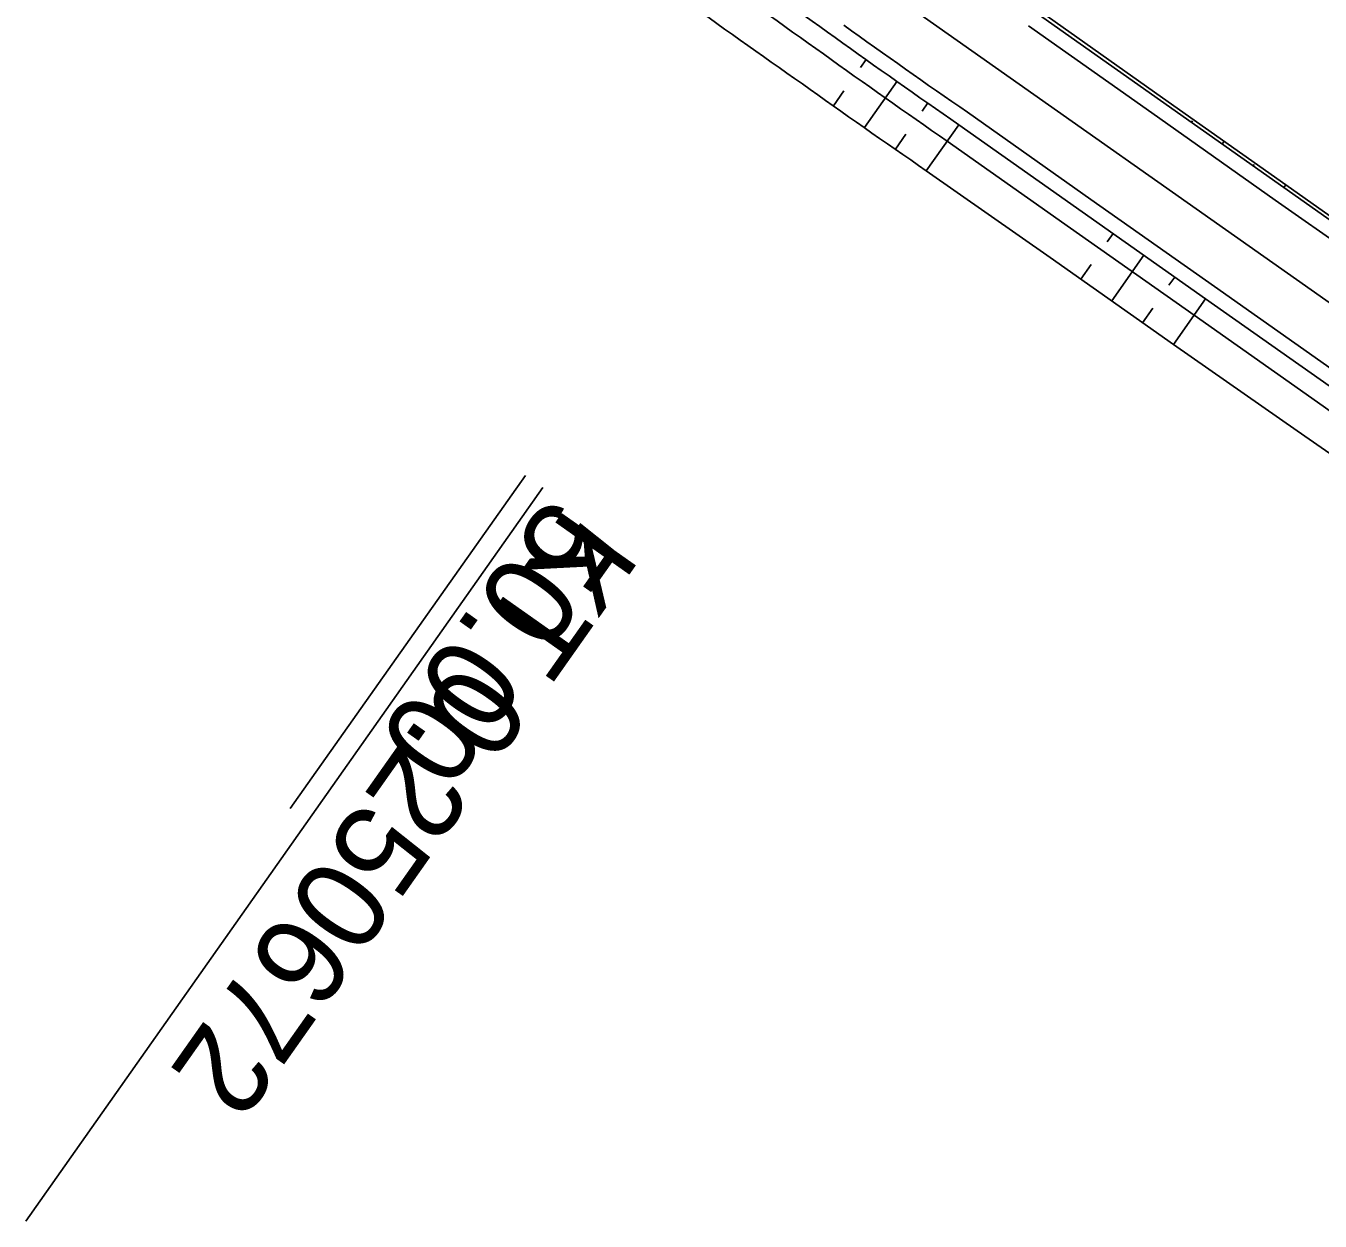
# Model space of a CAD drawing. Extents: x -481645 to -478728, y -1113199 to -1110710.
# Drawn here: x -480796.28 to -480753.43, y -1112781.89 to -1112742.33 of the extents above; entities that cross this region are included whole.
import ezdxf

# ---------------------------------------------------------------- set-up
doc = ezdxf.new("R2010")
doc.units = 0
for name, color, linetype in [('CP14_HATCH_SLOPE_R', 7, 'Continuous'), ('Vrstva 31', 7, 'Continuous'), ('Vrstva 32', 7, 'Continuous'), ('Vrstva 33', 7, 'Continuous'), ('Vrstva 34', 7, 'Continuous'), ('Vrstva 35', 7, 'Continuous'), ('Vrstva 36', 7, 'Continuous'), ('Vrstva 37', 7, 'Continuous'), ('Vrstva 39', 7, 'Continuous'), ('Vrstva 40', 7, 'Continuous')]:
    doc.layers.add(name, color=color, linetype=linetype)

msp = doc.modelspace()

# ---------------------------------------------------------------- linework, layer by layer
at = {"layer": 'CP14_HATCH_SLOPE_R'}
msp.add_line((-480767.637, -1112741.271), (-480724.708, -1112771.538), dxfattribs=at)
at = {"layer": 'Vrstva 31'}
for p, q in [((-480762.731, -1112741.823), (-480758.649, -1112744.712)), ((-480758.649, -1112744.712), (-480754.566, -1112747.598)), ((-480766.47, -1112747.127), (-480762.374, -1112749.995)), ((-480754.566, -1112747.598), (-480750.485, -1112750.486)), ((-480762.374, -1112749.995), (-480758.292, -1112752.882)), ((-480758.292, -1112752.882), (-480754.188, -1112755.739)), ((-480754.188, -1112755.739), (-480750.091, -1112758.604))]:
    msp.add_line(p, q, dxfattribs=at)
for centre, radius, start, end in [((-480480.966, -1112331.599), 504.14, 234.36572, 234.93868), ((-480624.003, -1112539.183), 252.066, 234.44634, 235.58416)]:
    msp.add_arc(centre, radius, start, end, dxfattribs=at)
at = {"layer": 'Vrstva 32'}
for p, q in [((-480765.78, -1112746.148), (-480761.694, -1112749.03)), ((-480761.694, -1112749.03), (-480757.607, -1112751.911)), ((-480757.607, -1112751.911), (-480753.521, -1112754.792)), ((-480753.521, -1112754.792), (-480749.434, -1112757.673))]:
    msp.add_line(p, q, dxfattribs=at)
for centre, radius, start, end in [((-480479.523, -1112332.626), 502.916, 234.16444, 234.7374), ((-480622.916, -1112539.216), 251.458, 234.23904, 235.37923)]:
    msp.add_arc(centre, radius, start, end, dxfattribs=at)
at = {"layer": 'Vrstva 33'}
for p, q in [((-480762.803, -1112741.926), (-480758.717, -1112744.807)), ((-480758.717, -1112744.807), (-480754.63, -1112747.688)), ((-480765.396, -1112745.604), (-480761.31, -1112748.485)), ((-480754.63, -1112747.688), (-480750.544, -1112750.569)), ((-480761.31, -1112748.485), (-480757.223, -1112751.366)), ((-480757.223, -1112751.366), (-480753.137, -1112754.247))]:
    msp.add_line(p, q, dxfattribs=at)
for centre, radius, start, end in [((-480479.523, -1112332.626), 502.25, 234.16444, 234.7374), ((-480622.724, -1112538.944), 251.125, 234.23839, 235.37989)]:
    msp.add_arc(centre, radius, start, end, dxfattribs=at)
at = {"layer": 'Vrstva 34'}
for p, q in [((-480763.091, -1112742.335), (-480759.005, -1112745.216)), ((-480765.108, -1112745.195), (-480761.021, -1112748.076)), ((-480759.005, -1112745.216), (-480754.918, -1112748.097)), ((-480761.021, -1112748.076), (-480756.935, -1112750.957)), ((-480754.918, -1112748.097), (-480750.832, -1112750.978)), ((-480756.935, -1112750.957), (-480752.849, -1112753.838))]:
    msp.add_line(p, q, dxfattribs=at)
msp.add_arc((-480622.579, -1112538.739), 250.875, 234.23791, 235.38038, dxfattribs=at)
at = {"layer": 'Vrstva 35'}
for p, q in [((-480763.091, -1112742.335), (-480759.005, -1112745.216)), ((-480765.108, -1112745.195), (-480761.021, -1112748.076)), ((-480759.005, -1112745.216), (-480754.918, -1112748.097)), ((-480761.021, -1112748.076), (-480756.935, -1112750.957)), ((-480754.918, -1112748.097), (-480750.832, -1112750.978)), ((-480756.935, -1112750.957), (-480752.849, -1112753.838))]:
    msp.add_line(p, q, dxfattribs=at)
msp.add_arc((-480622.579, -1112538.739), 250.875, 234.23791, 235.38038, dxfattribs=at)
at = {"layer": 'Vrstva 36'}
msp.add_line((-480779.732, -1112757.214), (-480787.526, -1112768.237), dxfattribs=at)
at = {"layer": 'Vrstva 37'}
msp.add_line((-480779.161, -1112757.617), (-480796.275, -1112781.89), dxfattribs=at)
at = {"layer": 'Vrstva 39'}
for p, q in [((-480757.695, -1112745.527), (-480757.662, -1112745.48)), ((-480757.629, -1112745.433), (-480757.629, -1112745.433)), ((-480756.673, -1112746.248), (-480756.608, -1112746.155)), ((-480755.652, -1112746.968), (-480755.62, -1112746.922)), ((-480755.587, -1112746.876), (-480755.587, -1112746.876)), ((-480754.63, -1112747.688), (-480754.566, -1112747.598))]:
    msp.add_line(p, q, dxfattribs=at)
at = {"layer": 'Vrstva 40'}
for p, q in [((-480768.461, -1112743.443), (-480768.653, -1112743.716)), ((-480769.194, -1112744.482), (-480769.542, -1112744.977)), ((-480767.439, -1112744.163), (-480768.518, -1112745.693)), ((-480766.418, -1112744.883), (-480766.61, -1112745.156)), ((-480765.396, -1112745.604), (-480766.47, -1112747.127)), ((-480767.148, -1112745.919), (-480767.494, -1112746.41)), ((-480760.288, -1112749.205), (-480760.48, -1112749.478)), ((-480759.266, -1112749.925), (-480760.333, -1112751.438)), ((-480761.013, -1112750.234), (-480761.354, -1112750.717)), ((-480758.245, -1112750.646), (-480758.437, -1112750.918)), ((-480757.223, -1112751.366), (-480758.292, -1112752.882)), ((-480758.971, -1112751.675), (-480759.313, -1112752.16))]:
    msp.add_line(p, q, dxfattribs=at)

# ---------------------------------------------------------------- texts
at = {"layer": 'Vrstva 36'}
msp.add_text('50.00', height=2.999, rotation=234.7374, dxfattribs=at).set_placement((-480778.915, -1112757.79))
at = {"layer": 'Vrstva 37'}
msp.add_text('KT 0.250672', height=2.999, rotation=234.8144, dxfattribs=at).set_placement((-480778.344, -1112758.192))

doc.saveas('drawing.dxf')
